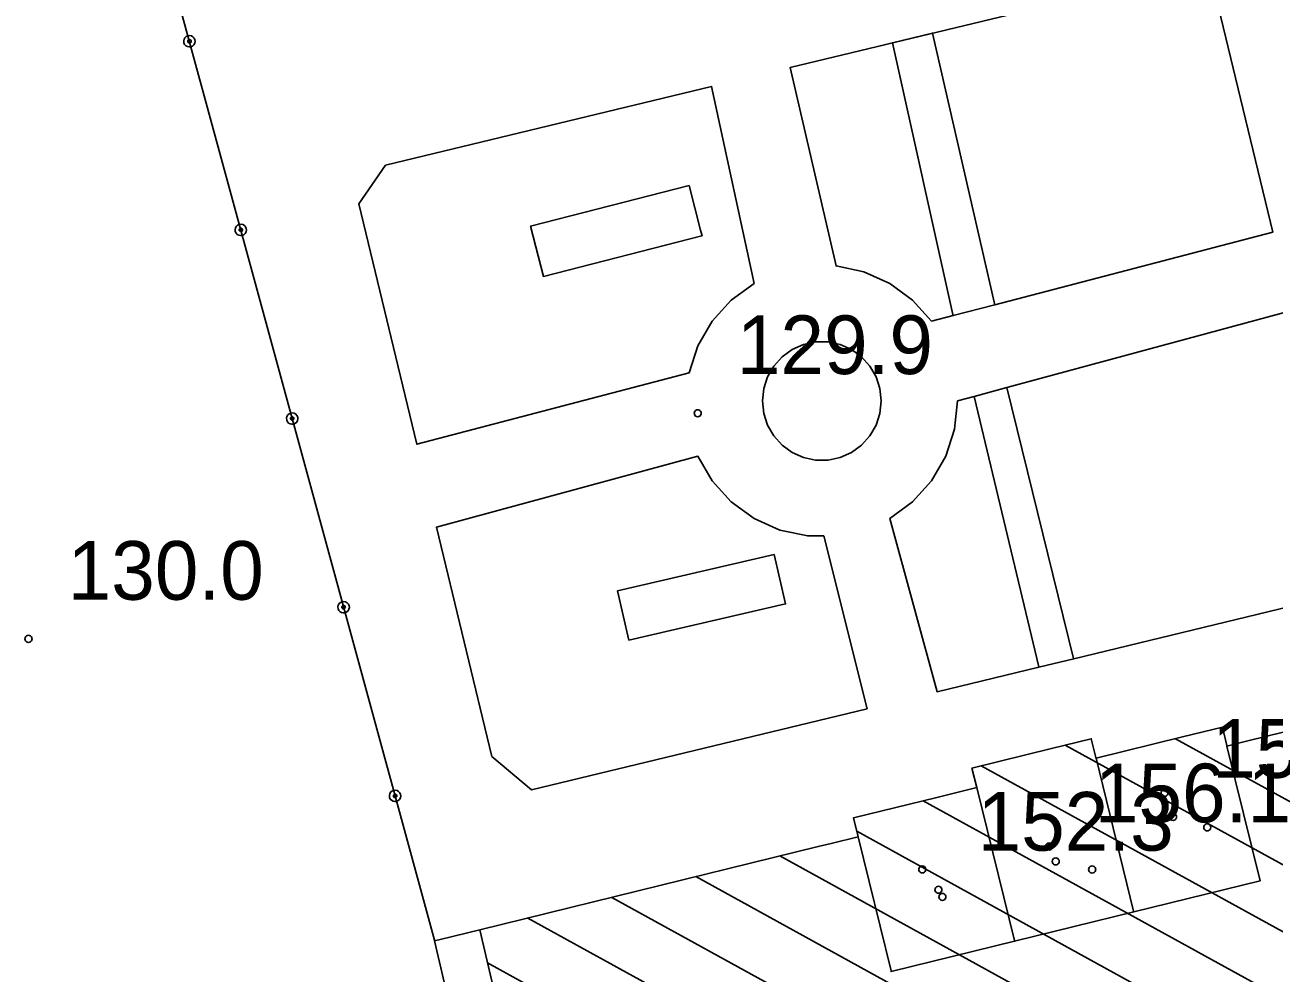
# Model space of a CAD drawing. Extents: x 513373 to 514978, y 5038576 to 5040180.
# Drawn here: x 513593.33 to 513625.28, y 5038613.29 to 5038637.54 of the extents above; entities that cross this region are included whole.
import ezdxf

# ---------------------------------------------------------------- set-up
doc = ezdxf.new("R2010")
doc.units = 0
for name, color, linetype in [('3010204', 7, 'Continuous'), ('B1211', 7, 'Continuous'), ('C1131', 7, 'Continuous'), ('C12211', 7, 'Continuous'), ('C211113', 7, 'Continuous'), ('C21117', 7, 'Continuous'), ('C2911', 7, 'Continuous'), ('C2912', 7, 'Continuous'), ('CAMP_C12211', 7, 'Continuous'), ('Default', 7, 'Continuous'), ('F12107', 7, 'Continuous'), ('F12131', 7, 'Continuous'), ('F12132', 7, 'Continuous'), ('TOP920', 7, 'Continuous')]:
    doc.layers.add(name, color=color, linetype=linetype)

# ---------------------------------------------------------------- blocks, each defined once
blk = doc.blocks.new('CAMP_71B7BAA1')
at = {"layer": 'CAMP_C12211'}
for p, q in [((8.843, -9.996), (-7.1, -1.232)), ((10.994, -9.468), (-4.284, -1.068)), ((6.691, -10.525), (-9.252, -1.761)), ((4.539, -11.054), (-10.74, -2.654)), ((2.388, -11.583), (-12.437, -3.433)), ((0.236, -12.112), (-14.4, -4.066)), ((-1.915, -12.641), (-16.551, -4.595)), ((-4.067, -13.17), (-18.703, -5.124)), ((-6.218, -13.699), (-20.854, -5.653)), ((-8.369, -14.228), (-21.878, -6.801))]:
    blk.add_line(p, q, dxfattribs=at)
blk = doc.blocks.new('03080200')
at = {"layer": 'Default'}
for p, q in [((-0.139, 0.046), (-0.146, 0)), ((-0.146, 0), (-0.139, -0.046)), ((-0.118, 0.086), (-0.139, 0.046)), ((-0.086, 0.118), (-0.118, 0.086)), ((-0.046, 0.139), (-0.086, 0.118)), ((0, 0.146), (-0.046, 0.139)), ((-0.042, 0.014), (-0.045, 0)), ((-0.045, 0), (-0.042, -0.014)), ((-0.036, 0.026), (-0.042, 0.014)), ((-0.026, 0.036), (-0.036, 0.026)), ((-0.014, 0.042), (-0.026, 0.036)), ((0, 0.045), (-0.014, 0.042)), ((0.046, 0.139), (0, 0.146)), ((0.014, 0.042), (0, 0.045)), ((0.026, 0.036), (0.014, 0.042)), ((0.036, 0.026), (0.026, 0.036)), ((0.042, 0.014), (0.036, 0.026)), ((0.045, 0), (0.042, 0.014)), ((0.042, -0.014), (0.045, 0)), ((0.086, 0.118), (0.046, 0.139)), ((0.118, 0.086), (0.086, 0.118)), ((0.139, 0.046), (0.118, 0.086)), ((0.146, 0), (0.139, 0.046)), ((0.139, -0.046), (0.146, 0)), ((-0.139, -0.046), (-0.118, -0.086)), ((-0.118, -0.086), (-0.086, -0.118)), ((-0.086, -0.118), (-0.046, -0.139)), ((-0.046, -0.139), (0, -0.146)), ((-0.042, -0.014), (-0.036, -0.026)), ((-0.036, -0.026), (-0.026, -0.036)), ((-0.026, -0.036), (-0.014, -0.042)), ((-0.014, -0.042), (0, -0.045)), ((0, -0.045), (0.014, -0.042)), ((0, -0.146), (0.046, -0.139)), ((0.014, -0.042), (0.026, -0.036)), ((0.026, -0.036), (0.036, -0.026)), ((0.036, -0.026), (0.042, -0.014)), ((0.046, -0.139), (0.086, -0.118)), ((0.086, -0.118), (0.118, -0.086)), ((0.118, -0.086), (0.139, -0.046))]:
    blk.add_line(p, q, dxfattribs=at)
blk = doc.blocks.new('08020400')
at = {"layer": 'Default'}
for p, q in [((-0.086, 0.028), (-0.09, 0)), ((-0.09, 0), (-0.086, -0.028)), ((-0.073, 0.053), (-0.086, 0.028)), ((-0.053, 0.073), (-0.073, 0.053)), ((-0.028, 0.086), (-0.053, 0.073)), ((0, 0.09), (-0.028, 0.086)), ((0.028, 0.086), (0, 0.09)), ((0.053, 0.073), (0.028, 0.086)), ((0.073, 0.053), (0.053, 0.073)), ((0.086, 0.028), (0.073, 0.053)), ((0.09, 0), (0.086, 0.028)), ((0.086, -0.028), (0.09, 0)), ((-0.086, -0.028), (-0.073, -0.053)), ((-0.073, -0.053), (-0.053, -0.073)), ((-0.053, -0.073), (-0.028, -0.086)), ((-0.028, -0.086), (0, -0.09)), ((0, -0.09), (0.028, -0.086)), ((0.028, -0.086), (0.053, -0.073)), ((0.053, -0.073), (0.073, -0.053)), ((0.073, -0.053), (0.086, -0.028))]:
    blk.add_line(p, q, dxfattribs=at)
blk = doc.blocks.new('NSIMB25')
at = {"layer": 'Default'}
for p, q in [((-0.086, 0.028), (-0.09, 0)), ((-0.09, 0), (-0.086, -0.028)), ((-0.073, 0.053), (-0.086, 0.028)), ((-0.053, 0.073), (-0.073, 0.053)), ((-0.028, 0.086), (-0.053, 0.073)), ((0, 0.09), (-0.028, 0.086)), ((0.028, 0.086), (0, 0.09)), ((0.053, 0.073), (0.028, 0.086)), ((0.073, 0.053), (0.053, 0.073)), ((0.086, 0.028), (0.073, 0.053)), ((0.09, 0), (0.086, 0.028)), ((0.086, -0.028), (0.09, 0)), ((-0.086, -0.028), (-0.073, -0.053)), ((-0.073, -0.053), (-0.053, -0.073)), ((-0.053, -0.073), (-0.028, -0.086)), ((-0.028, -0.086), (0, -0.09)), ((0, -0.09), (0.028, -0.086)), ((0.028, -0.086), (0.053, -0.073)), ((0.053, -0.073), (0.073, -0.053)), ((0.073, -0.053), (0.086, -0.028))]:
    blk.add_line(p, q, dxfattribs=at)
blk = doc.blocks.new('A$C3704598A')
at = {"layer": '3010204'}
for points in [[(243.479, -750.179), (242.993, -749.64), (242.406, -749.213), (241.743, -748.918), (241.034, -748.767), (239.861, -743.689), (249.651, -741.327), (250.751, -741.869), (252.207, -747.899), (245.095, -749.757), (244.033, -750.035), (243.479, -750.179)], [(237.276, -751.497), (237.5, -750.807), (237.863, -750.178), (238.348, -749.639), (238.935, -749.213), (237.85, -744.175), (229.51, -746.188), (228.821, -747.181), (230.305, -753.326), (237.276, -751.497)], [(244.141, -752.219), (244.566, -752.105), (245.406, -751.878), (252.691, -749.907), (254.191, -756.119), (253.491, -757.273), (247.115, -758.812), (246.222, -759.027), (243.621, -759.655), (242.406, -755.224), (242.993, -754.798), (243.479, -754.26), (243.841, -753.631), (244.066, -752.941), (244.141, -752.219)], [(240.724, -755.67), (241.827, -760.087), (233.239, -762.16), (232.231, -761.308), (230.815, -755.441), (237.5, -753.63), (237.863, -754.259), (238.348, -754.798), (238.935, -755.224), (239.598, -755.519), (240.308, -755.67), (240.724, -755.67)]]:
    blk.add_lwpolyline(points, dxfattribs=at)
at = {"layer": 'B1211'}
blk.add_lwpolyline([(233.647, -778.325), (230.763, -766.025), (230.903, -765.991), (231.922, -765.74), (234.5, -776.734)], dxfattribs=at)
at = {"layer": 'C1131'}
for points in [[(272.425, -768.805), (271.852, -768.961), (271.43, -769.053), (233.651, -778.34), (233.647, -778.325), (230.763, -766.025), (230.903, -765.991), (231.922, -765.74), (234.5, -776.734), (234.504, -776.749), (247.715, -773.503), (250.181, -772.896), (270.537, -767.892), (271.988, -765.243), (263.897, -737.693), (264.178, -737.61), (265.184, -737.315), (273.432, -765.399)], [(234.5, -776.734), (231.922, -765.74), (240.578, -763.612), (240.91, -763.53), (241.597, -763.361), (242.44, -766.793), (242.444, -766.808), (245.6, -766.033), (248.652, -765.283), (251.883, -764.489), (251.035, -761.042), (251.567, -760.911), (256.193, -759.774)]]:
    blk.add_lwpolyline(points, dxfattribs=at)
for points in [[(251.035, -761.042), (251.883, -764.489), (248.652, -765.283), (248.648, -765.267), (247.686, -761.354), (249.898, -760.81), (250.917, -760.56), (251.031, -761.026)], [(247.686, -761.354), (248.648, -765.267), (248.652, -765.283), (245.6, -766.033), (245.596, -766.017), (244.634, -762.104), (244.512, -761.606), (246.545, -761.106), (247.564, -760.856), (247.682, -761.338)], [(245.6, -766.033), (242.444, -766.808), (242.44, -766.793), (241.597, -763.361), (241.478, -762.879), (243.615, -762.354), (244.634, -762.104), (245.596, -766.017)]]:
    blk.add_lwpolyline(points, close=True, dxfattribs=at)
at = {"layer": 'C12211'}
blk.add_lwpolyline([(234.5, -776.734), (231.922, -765.74), (240.578, -763.612), (240.91, -763.53), (241.597, -763.361), (241.478, -762.879), (243.615, -762.354), (244.634, -762.104), (244.512, -761.606), (246.545, -761.106), (247.564, -760.856), (247.682, -761.338), (247.686, -761.354), (249.898, -760.81), (250.917, -760.56), (251.031, -761.026), (251.035, -761.042), (251.567, -760.911), (256.193, -759.774)], dxfattribs=at)
at = {"layer": 'C211113'}
for points in [[(244.033, -750.035), (244.026, -750.004), (242.476, -743.058), (243.5, -742.811), (245.088, -749.726), (245.095, -749.757)], [(237.274, -746.705), (233.217, -747.745), (233.547, -749.033), (237.599, -747.996), (237.605, -747.994), (237.567, -747.848)], [(246.222, -759.027), (246.219, -759.016), (244.566, -752.105), (245.406, -751.878), (247.112, -758.8), (247.115, -758.812)], [(235.731, -758.336), (239.744, -757.408), (239.453, -756.148), (235.439, -757.076)]]:
    blk.add_lwpolyline(points, close=True, dxfattribs=at)
at = {"layer": 'C21117'}
blk.add_lwpolyline([(240.83, -753.73), (240.512, -753.73), (240.201, -753.664), (239.911, -753.535), (239.654, -753.348), (239.441, -753.112), (239.282, -752.837), (239.184, -752.535), (239.151, -752.218), (239.184, -751.902), (239.282, -751.6), (239.441, -751.325), (239.654, -751.089), (239.911, -750.902), (240.201, -750.773), (240.512, -750.707), (240.83, -750.707), (241.141, -750.773), (241.431, -750.902), (241.688, -751.089), (241.901, -751.325), (242.059, -751.6), (242.158, -751.902), (242.191, -752.218), (242.158, -752.535), (242.059, -752.837), (241.901, -753.112), (241.688, -753.348), (241.431, -753.535), (241.141, -753.664)], close=True, dxfattribs=at)
at = {"layer": 'C2911'}
blk.add_lwpolyline([(230.763, -766.025), (230.903, -765.991), (231.922, -765.74)], dxfattribs=at)
at = {"layer": 'C2912'}
blk.add_lwpolyline([(222.557, -735.774), (223.55, -739.57), (230.759, -766.01), (230.763, -766.025)], dxfattribs=at)
at = {"layer": 'C2912', "rotation": -74.74971665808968}
for p in [(224.491, -743.021), (225.806, -747.844), (227.121, -752.668), (228.436, -757.492), (229.752, -762.316)]:
    blk.add_blockref('03080200', p, dxfattribs=at)
at = {"layer": 'CAMP_C12211'}
blk.add_blockref('CAMP_71B7BAA1', (253.999, -759.787), dxfattribs=at)
at = {"layer": 'F12107'}
for p in [(237.495, -752.531), (220.374, -758.301), (249.655, -762.854), (246.654, -763.992), (243.654, -764.717)]:
    blk.add_blockref('08020400', p, dxfattribs=at)
at = {"layer": 'F12131'}
for p in [(250.53, -763.12), (246.483, -763.614), (243.755, -764.899)]:
    blk.add_blockref('NSIMB25', p, dxfattribs=at)
at = {"layer": 'F12132'}
for p in [(249.439, -762.238), (243.24, -764.198), (247.586, -764.199)]:
    blk.add_blockref('NSIMB25', p, dxfattribs=at)
at = {"layer": 'TOP920'}
for s, p in [('129.9', (238.495, -751.531)), ('130.0', (221.374, -757.301)), ('152.3', (250.655, -761.854)), ('156.1', (247.654, -762.992)), ('152.3', (244.654, -763.717))]:
    blk.add_text(s, height=1.5, dxfattribs=at).set_placement(p)

msp = doc.modelspace()

# ---------------------------------------------------------------- block references
at = {"layer": 'Default'}
msp.add_blockref('A$C3704598A', (513373.046, 5039380.14), dxfattribs=at)

doc.saveas('drawing.dxf')
